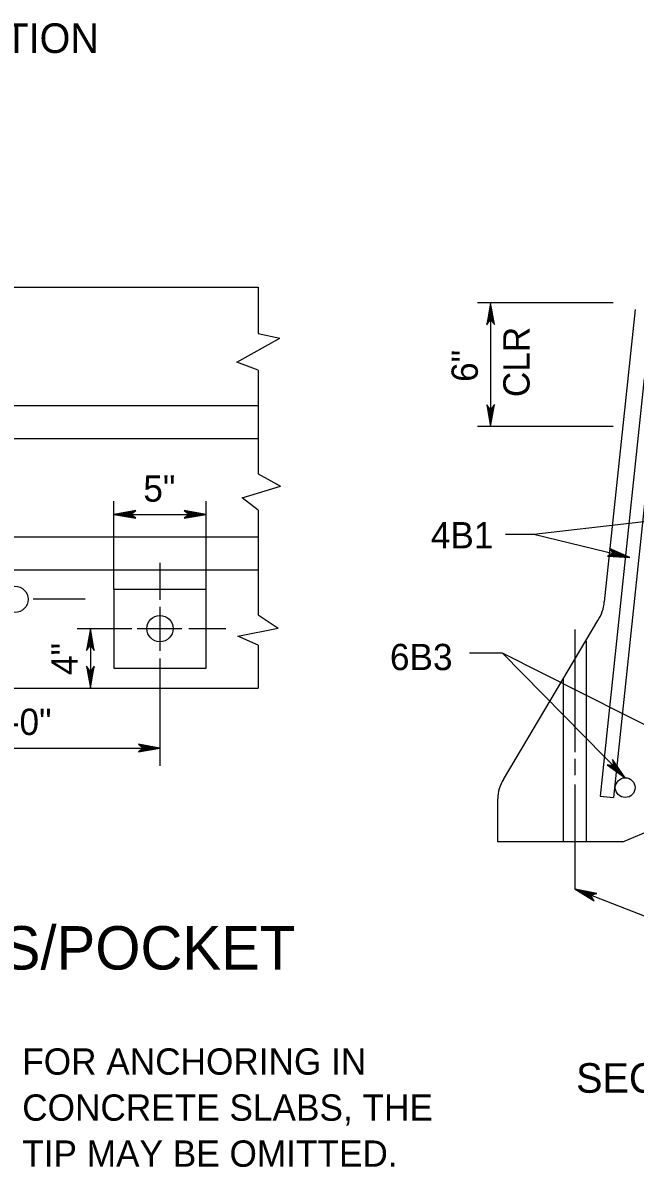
# Model space of a CAD drawing. Extents: x 499883 to 500983, y 499104 to 499764.
# Drawn here: x 500135.2 to 500228.2, y 499394.8 to 499568.8 of the extents above; entities that cross this region are included whole.
import ezdxf

# ---------------------------------------------------------------- set-up
doc = ezdxf.new("R2010")
doc.units = 0
for name, color, linetype in [('24', 7, 'Continuous'), ('5', 7, 'Continuous'), ('60', 7, 'Continuous')]:
    doc.layers.add(name, color=color, linetype=linetype)

msp = doc.modelspace()

# ---------------------------------------------------------------- linework, layer by layer
at = {"layer": '24'}
for points in [[(500206.23, 499526.24), (500205.65, 499522.92), (500206.23, 499523.71), (500206.81, 499522.94), (500206.23, 499526.24), (500206.24, 499526.02), (500205.69, 499523.01), (500206.24, 499523.77), (500206.77, 499523.07), (500206.25, 499525.9), (500206.23, 499525.79), (500205.78, 499523.21), (500206.24, 499523.79), (500206.69, 499523.2), (500206.23, 499525.74), (500206.25, 499525.63), (500205.84, 499523.38), (500206.23, 499523.81), (500206.64, 499523.37), (500206.25, 499525.31), (500206.25, 499525.12), (500205.93, 499523.54), (500206.23, 499523.85), (500206.56, 499523.52), (500206.23, 499525.09), (500206.22, 499524.91), (500206.02, 499523.72), (500206.25, 499523.95), (500206.48, 499523.71), (500206.23, 499524.75), (500206.22, 499524.58), (500206.08, 499523.87), (500206.24, 499523.99), (500206.42, 499523.79), (500206.23, 499524.49), (500206.12, 499524.03), (500206.25, 499524.1), (500206.38, 499523.89), (500206.25, 499524.38), (500206.17, 499524.07), (500206.28, 499524.2), (500206.34, 499524.05), (500206.24, 499524.2), (500206.23, 499524.12)], [(500206.23, 499526.24), (500205.65, 499522.92), (500206.23, 499523.71), (500206.81, 499522.94), (500206.23, 499526.24), (500206.24, 499526.02), (500205.69, 499523.01), (500206.24, 499523.77), (500206.77, 499523.07), (500206.25, 499525.9), (500206.23, 499525.79), (500205.78, 499523.21), (500206.24, 499523.79), (500206.69, 499523.2), (500206.23, 499525.74), (500206.25, 499525.63), (500205.84, 499523.38), (500206.23, 499523.81), (500206.64, 499523.37), (500206.25, 499525.31), (500206.25, 499525.12), (500205.93, 499523.54), (500206.23, 499523.85), (500206.56, 499523.52), (500206.23, 499525.09), (500206.22, 499524.91), (500206.02, 499523.72), (500206.25, 499523.95), (500206.48, 499523.71), (500206.23, 499524.75), (500206.22, 499524.58), (500206.08, 499523.87), (500206.24, 499523.99), (500206.42, 499523.79), (500206.23, 499524.49), (500206.12, 499524.03), (500206.25, 499524.1), (500206.38, 499523.89), (500206.25, 499524.38), (500206.17, 499524.07), (500206.28, 499524.2), (500206.34, 499524.05), (500206.24, 499524.2), (500206.23, 499524.12)], [(500206.23, 499507.47), (500206.82, 499510.79), (500206.23, 499509.99), (500205.66, 499510.77), (500206.23, 499507.47), (500206.23, 499507.69), (500206.78, 499510.7), (500206.23, 499509.93), (500205.7, 499510.64), (500206.22, 499507.81), (500206.23, 499507.92), (500206.69, 499510.49), (500206.23, 499509.92), (500205.78, 499510.51), (500206.23, 499507.97), (500206.22, 499508.08), (500206.62, 499510.33), (500206.23, 499509.89), (500205.83, 499510.34), (500206.22, 499508.4), (500206.22, 499508.59), (500206.54, 499510.16), (500206.24, 499509.86), (500205.91, 499510.19), (500206.23, 499508.62), (500206.24, 499508.8), (500206.45, 499509.98), (500206.22, 499509.75), (500205.99, 499510), (500206.23, 499508.96), (500206.25, 499509.13), (500206.39, 499509.84), (500206.23, 499509.72), (500206.05, 499509.92), (500206.23, 499509.21), (500206.34, 499509.68), (500206.22, 499509.61), (500206.09, 499509.82), (500206.22, 499509.33), (500206.29, 499509.64), (500206.19, 499509.51), (500206.13, 499509.65), (500206.23, 499509.51), (500206.24, 499509.59)], [(500206.23, 499507.47), (500206.82, 499510.79), (500206.23, 499509.99), (500205.66, 499510.77), (500206.23, 499507.47), (500206.23, 499507.69), (500206.78, 499510.7), (500206.23, 499509.93), (500205.7, 499510.64), (500206.22, 499507.81), (500206.23, 499507.92), (500206.69, 499510.49), (500206.23, 499509.92), (500205.78, 499510.51), (500206.23, 499507.97), (500206.22, 499508.08), (500206.62, 499510.33), (500206.23, 499509.89), (500205.83, 499510.34), (500206.22, 499508.4), (500206.22, 499508.59), (500206.54, 499510.16), (500206.24, 499509.86), (500205.91, 499510.19), (500206.23, 499508.62), (500206.24, 499508.8), (500206.45, 499509.98), (500206.22, 499509.75), (500205.99, 499510), (500206.23, 499508.96), (500206.25, 499509.13), (500206.39, 499509.84), (500206.23, 499509.72), (500206.05, 499509.92), (500206.23, 499509.21), (500206.34, 499509.68), (500206.22, 499509.61), (500206.09, 499509.82), (500206.22, 499509.33), (500206.29, 499509.64), (500206.19, 499509.51), (500206.13, 499509.65), (500206.23, 499509.51), (500206.24, 499509.59)], [(500149, 499494.08), (500152.32, 499493.5), (500151.53, 499494.08), (500152.3, 499494.66), (500149, 499494.08), (500149.22, 499494.09), (500152.23, 499493.54), (500151.46, 499494.09), (500152.17, 499494.62), (500149.34, 499494.1), (500149.45, 499494.08), (500152.03, 499493.63), (500151.45, 499494.09), (500152.04, 499494.54), (500149.5, 499494.08), (500149.61, 499494.1), (500151.86, 499493.69), (500151.42, 499494.08), (500151.87, 499494.49), (500149.93, 499494.1), (500150.12, 499494.1), (500151.7, 499493.78), (500151.39, 499494.07), (500151.72, 499494.4), (500150.15, 499494.08), (500150.33, 499494.07), (500151.52, 499493.87), (500151.29, 499494.1), (500151.53, 499494.33), (500150.49, 499494.08), (500150.66, 499494.07), (500151.37, 499493.93), (500151.25, 499494.09), (500151.45, 499494.27), (500150.75, 499494.08), (500151.21, 499493.97), (500151.14, 499494.1), (500151.35, 499494.23), (500150.86, 499494.1), (500151.17, 499494.02), (500151.04, 499494.12), (500151.19, 499494.18), (500151.04, 499494.09), (500151.12, 499494.07)], [(500162.99, 499494.08), (500159.66, 499494.67), (500160.46, 499494.08), (500159.68, 499493.51), (500162.99, 499494.08), (500162.77, 499494.08), (500159.76, 499494.63), (500160.52, 499494.08), (500159.81, 499493.55), (500162.65, 499494.07), (500162.54, 499494.08), (500159.96, 499494.54), (500160.54, 499494.08), (500159.94, 499493.63), (500162.49, 499494.08), (500162.38, 499494.07), (500160.12, 499494.47), (500160.56, 499494.08), (500160.11, 499493.68), (500162.05, 499494.07), (500161.87, 499494.07), (500160.29, 499494.39), (500160.6, 499494.09), (500160.26, 499493.76), (500161.83, 499494.08), (500161.66, 499494.09), (500160.47, 499494.3), (500160.7, 499494.07), (500160.45, 499493.84), (500161.49, 499494.08), (500161.32, 499494.1), (500160.61, 499494.24), (500160.73, 499494.08), (500160.54, 499493.9), (500161.24, 499494.08), (500160.77, 499494.19), (500160.84, 499494.07), (500160.64, 499493.94), (500161.12, 499494.07), (500160.82, 499494.14), (500160.94, 499494.04), (500160.8, 499493.98), (500160.94, 499494.08), (500160.87, 499494.09)], [(500145.42, 499476.72), (500144.83, 499473.39), (500145.42, 499474.19), (500146, 499473.41), (500145.42, 499476.72), (500145.43, 499476.5), (500144.88, 499473.49), (500145.43, 499474.25), (500145.95, 499473.54), (500145.44, 499476.38), (500145.42, 499476.27), (500144.96, 499473.69), (500145.43, 499474.27), (500145.88, 499473.67), (500145.42, 499476.22), (500145.44, 499476.11), (500145.03, 499473.85), (500145.42, 499474.29), (500145.83, 499473.84), (500145.44, 499475.78), (500145.44, 499475.6), (500145.11, 499474.02), (500145.41, 499474.33), (500145.74, 499474), (500145.42, 499475.56), (500145.41, 499475.39), (500145.21, 499474.2), (500145.44, 499474.43), (500145.67, 499474.18), (500145.42, 499475.22), (500145.4, 499475.06), (500145.27, 499474.34), (500145.43, 499474.46), (500145.61, 499474.27), (500145.42, 499474.97), (500145.31, 499474.5), (500145.44, 499474.57), (500145.57, 499474.37), (500145.44, 499474.85), (500145.36, 499474.55), (500145.46, 499474.67), (500145.52, 499474.53), (500145.43, 499474.67), (500145.41, 499474.6)], [(500145.42, 499467.68), (500146.01, 499471), (500145.42, 499470.21), (500144.84, 499470.98), (500145.42, 499467.68), (500145.42, 499467.9), (500145.97, 499470.91), (500145.41, 499470.15), (500144.89, 499470.85), (500145.41, 499468.02), (500145.42, 499468.13), (500145.88, 499470.71), (500145.41, 499470.13), (500144.96, 499470.72), (500145.42, 499468.18), (500145.41, 499468.29), (500145.81, 499470.54), (500145.42, 499470.11), (500145.02, 499470.55), (500145.4, 499468.61), (500145.4, 499468.8), (500145.73, 499470.38), (500145.43, 499470.07), (500145.1, 499470.4), (500145.42, 499468.83), (500145.43, 499469.01), (500145.63, 499470.2), (500145.4, 499469.97), (500145.18, 499470.21), (500145.42, 499469.17), (500145.44, 499469.34), (500145.57, 499470.05), (500145.41, 499469.93), (500145.24, 499470.13), (500145.42, 499469.43), (500145.53, 499469.89), (500145.4, 499469.82), (500145.28, 499470.03), (500145.4, 499469.54), (500145.48, 499469.85), (500145.38, 499469.72), (500145.32, 499469.87), (500145.41, 499469.72), (500145.43, 499469.8)], [(500155.99, 499458.54), (500152.72, 499459.12), (500153.5, 499458.54), (500152.73, 499457.97), (500155.99, 499458.54), (500155.77, 499458.53), (500152.81, 499459.07), (500153.56, 499458.53), (500152.87, 499458.01), (500155.66, 499458.52), (500155.55, 499458.54), (500153.01, 499458.99), (500153.58, 499458.53), (500152.99, 499458.09), (500155.5, 499458.54), (500155.39, 499458.52), (500153.17, 499458.92), (500153.6, 499458.54), (500153.16, 499458.14), (500155.07, 499458.52), (500154.89, 499458.52), (500153.33, 499458.84), (500153.64, 499458.55), (500153.31, 499458.22), (500154.86, 499458.54), (500154.68, 499458.55), (500153.51, 499458.75), (500153.74, 499458.52), (500153.49, 499458.3), (500154.52, 499458.54), (500154.36, 499458.56), (500153.65, 499458.69), (500153.77, 499458.53), (500153.58, 499458.36), (500154.27, 499458.54), (500153.81, 499458.65), (500153.88, 499458.52), (500153.68, 499458.4), (500154.15, 499458.52), (500153.85, 499458.6), (500153.98, 499458.5), (500153.84, 499458.44), (500153.98, 499458.53), (500153.9, 499458.55)]]:
    msp.add_lwpolyline(points, dxfattribs=at)
at = {"layer": '5'}
for p, q in [((500080.99, 499528.63), (500170.92, 499528.63)), ((500170.92, 499528.63), (500170.92, 499521.57)), ((500224.88, 499526.24), (500204.24, 499526.24)), ((500224.88, 499526.24), (500204.24, 499526.24)), ((500206.23, 499526.24), (500206.23, 499507.47)), ((500206.23, 499526.24), (500206.23, 499507.47)), ((500228.22, 499525.25), (500223.52, 499480.81)), ((500167.69, 499517.23), (500174.2, 499520.89)), ((500170.92, 499521.57), (500174.2, 499520.89)), ((500170.92, 499516.01), (500167.69, 499517.23)), ((500170.92, 499516.01), (500170.92, 499500.27)), ((500229.6, 499514.73), (500222.91, 499451.25)), ((500231.6, 499514.45), (500224.9, 499451.04)), ((500080.99, 499510.65), (500170.92, 499510.65)), ((500224.88, 499507.47), (500204.24, 499507.47)), ((500224.88, 499507.47), (500204.24, 499507.47)), ((500080.99, 499505.65), (500170.92, 499505.65)), ((500170.92, 499500.27), (500174.33, 499498.37)), ((500168.5, 499496.61), (500174.33, 499498.37)), ((500170.92, 499494.71), (500168.5, 499496.61)), ((500149, 499482.71), (500149, 499496.08)), ((500162.99, 499482.71), (500162.99, 499496.08)), ((500149, 499494.08), (500162.99, 499494.08)), ((500170.92, 499494.71), (500170.92, 499478.83)), ((500080.99, 499490.66), (500170.92, 499490.66)), ((500212.8, 499491.1), (500227.38, 499487.51)), ((500155.99, 499486.71), (500155.99, 499481.1)), ((500080.99, 499485.66), (500170.92, 499485.66)), ((500149, 499482.71), (500162.99, 499482.71)), ((500149, 499482.71), (500149, 499470.72)), ((500162.99, 499470.72), (500162.99, 499482.71)), ((500144.62, 499481.17), (500136.73, 499481.17)), ((500155.99, 499480.04), (500155.99, 499473.36)), ((500170.92, 499478.83), (500173.93, 499476.8)), ((500208.19, 499453.78), (500222.56, 499477.97)), ((500143.42, 499476.72), (500151.7, 499476.72)), ((500145.42, 499476.72), (500145.42, 499467.68)), ((500152.54, 499476.72), (500159.33, 499476.72)), ((500160.39, 499476.72), (500165.98, 499476.72)), ((500167.82, 499475.58), (500173.93, 499476.8)), ((500219.08, 499457.93), (500219.08, 499476.6)), ((500170.92, 499474.22), (500167.82, 499475.58)), ((500170.92, 499474.22), (500170.92, 499467.68)), ((500220.83, 499444.3), (500220.83, 499474.81)), ((500155.99, 499472.19), (500155.99, 499455.84)), ((500207.98, 499473.01), (500226.7, 499454.03)), ((500149, 499470.72), (500162.99, 499470.72)), ((500217.33, 499444.3), (500217.33, 499469.24)), ((500080.99, 499467.68), (500170.92, 499467.68)), ((500113.51, 499458.54), (500155.99, 499458.54)), ((500219.08, 499454.44), (500219.08, 499456.89)), ((500219.08, 499437.1), (500219.08, 499453.02)), ((500222.91, 499451.25), (500224.9, 499451.04)), ((500207.34, 499444.3), (500207.34, 499450.84)), ((500226.33, 499444.3), (500235.82, 499448.3)), ((500226.33, 499444.3), (500207.34, 499444.3))]:
    msp.add_line(p, q, dxfattribs=at)
for points in [[(500208.51, 499491.1), (500212.8, 499491.1), (500242.69, 499494.51)], [(500227.38, 499487.51), (500224.29, 499488.88), (500224.92, 499488.12), (500224.03, 499487.74), (500227.38, 499487.51), (500227.17, 499487.56), (500224.37, 499488.81), (500224.98, 499488.1), (500224.17, 499487.75), (500227.05, 499487.58), (500226.94, 499487.62), (500224.55, 499488.68), (500225, 499488.09), (500224.31, 499487.8), (500226.89, 499487.63), (500226.78, 499487.64), (500224.69, 499488.58), (500225.02, 499488.09), (500224.49, 499487.81), (500226.47, 499487.72), (500226.29, 499487.76), (500224.84, 499488.46), (500225.06, 499488.09), (500224.66, 499487.85), (500226.26, 499487.79), (500226.09, 499487.84), (500224.99, 499488.32), (500225.15, 499488.04), (500224.86, 499487.88), (500225.93, 499487.87), (500225.77, 499487.93), (500225.11, 499488.23), (500225.19, 499488.05), (500224.96, 499487.92), (500225.68, 499487.93), (500225.26, 499488.15), (500225.29, 499488.01), (500225.07, 499487.94), (500225.57, 499487.94), (500225.29, 499488.09), (500225.39, 499487.96), (500225.23, 499487.94), (500225.4, 499487.99), (500225.33, 499488.03)], [(500203.03, 499473.01), (500207.98, 499473.01), (500244.98, 499454.36)], [(500226.7, 499454.03), (500224.78, 499456.81), (500224.92, 499455.83), (500223.96, 499455.98), (500226.7, 499454.03), (500226.54, 499454.19), (500224.82, 499456.71), (500224.96, 499455.78), (500224.09, 499455.92), (500226.45, 499454.26), (500226.38, 499454.35), (500224.9, 499456.51), (500224.97, 499455.77), (500224.23, 499455.88), (500226.34, 499454.39), (500226.26, 499454.46), (500224.96, 499456.35), (500224.99, 499455.76), (500224.39, 499455.79), (500226.03, 499454.68), (500225.9, 499454.82), (500225.02, 499456.17), (500225.02, 499455.74), (500224.56, 499455.74), (500225.89, 499454.85), (500225.77, 499454.99), (500225.08, 499455.97), (500225.08, 499455.65), (500224.74, 499455.67), (500225.65, 499455.1), (500225.54, 499455.23), (500225.14, 499455.83), (500225.11, 499455.63), (500224.84, 499455.65), (500225.47, 499455.28), (500225.22, 499455.69), (500225.18, 499455.55), (500224.94, 499455.6), (500225.37, 499455.35), (500225.21, 499455.62), (500225.23, 499455.46), (500225.09, 499455.52), (500225.26, 499455.48), (500225.21, 499455.55)], [(500219.08, 499437.1), (500221.96, 499435.34), (500221.44, 499436.18), (500222.37, 499436.43), (500219.08, 499437.1), (500219.29, 499437.02), (500221.89, 499435.42), (500221.38, 499436.21), (500222.23, 499436.44), (500219.4, 499436.99), (500219.5, 499436.93), (500221.74, 499435.57), (500221.37, 499436.21), (500222.09, 499436.42), (500219.55, 499436.91), (500219.66, 499436.89), (500221.61, 499435.69), (500221.34, 499436.21), (500221.91, 499436.43), (500219.96, 499436.77), (500220.13, 499436.7), (500221.48, 499435.83), (500221.31, 499436.22), (500221.73, 499436.41), (500220.16, 499436.68), (500220.32, 499436.6), (500221.35, 499435.98), (500221.22, 499436.28), (500221.53, 499436.4), (500220.47, 499436.55), (500220.62, 499436.48), (500221.24, 499436.09), (500221.19, 499436.28), (500221.43, 499436.38), (500220.71, 499436.46), (500221.1, 499436.19), (500221.09, 499436.33), (500221.32, 499436.38), (500220.83, 499436.43), (500221.08, 499436.25), (500221, 499436.39), (500221.16, 499436.39), (500220.99, 499436.36), (500221.05, 499436.32)], [(500243.35, 499429.58), (500238.36, 499429.58), (500219.08, 499437.1)]]:
    msp.add_lwpolyline(points, dxfattribs=at)
for centre in [(500133.95, 499481.17), (500155.99, 499476.72)]:
    msp.add_circle(centre, 2, dxfattribs=at)
for centre, start, end in [((500217.54, 499481.26), 326.725, 355.6264), ((500213.32, 499450.68), 148.8582, 178.4586)]:
    msp.add_arc(centre, 6, start, end, dxfattribs=at)
at = {"layer": '60'}
msp.add_circle((500226.7, 499452.53), 1.5, dxfattribs=at)

# ---------------------------------------------------------------- texts
at = {"layer": '5'}
for s, height, p in [('ELEVATION', 4.5, (500112.94, 499564.26)), ('5"', 4, (500153.46, 499496.02)), ('4B1', 4, (500197.15, 499488.92)), ('6B3', 4, (500190.94, 499470.4)), ('2\'-0"', 4, (500128.86, 499460.54)), ('PLAN-ANCHOR RECESS/POCKET', 6.6001, (500034.83, 499424.87)), ('FOR ANCHORING IN', 4, (500135.05, 499408.88)), ('SECTION A-A', 4.5, (500219.24, 499406.13)), ('CONCRETE SLABS, THE', 4, (500135.05, 499401.88)), ('TIP MAY BE OMITTED.', 4, (500135.05, 499394.88))]:
    msp.add_text(s, height=height, dxfattribs=at).set_placement(p)
for s, p in [('CLR', (500212.17, 499511.92)), ('6"', (500204.3, 499514.23)), ('4"', (500143.48, 499469.66))]:
    msp.add_text(s, height=4, rotation=90, dxfattribs=at).set_placement(p)

doc.saveas('drawing.dxf')
